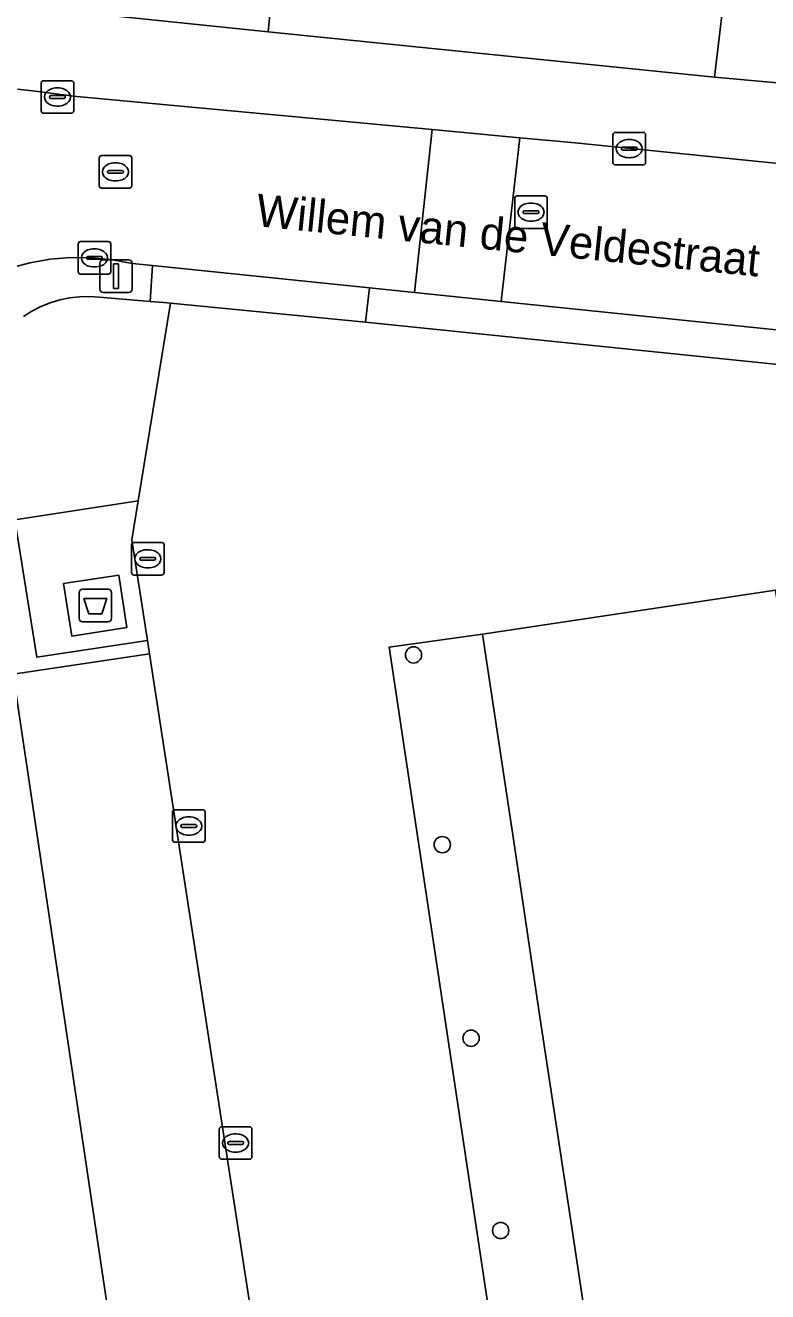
# Model space of a CAD drawing. Extents: x 163008 to 163854, y 382777 to 383982.
# Drawn here: x 163190.97 to 163213.77, y 383368.33 to 383407.26 of the extents above; entities that cross this region are included whole.
import ezdxf

# ---------------------------------------------------------------- set-up
doc = ezdxf.new("R2010")
doc.units = 0
for name, color, linetype in [('IMGEO_Afval_apart_plaats', 7, 'Continuous'), ('IMGEO_Groenvoorziening', 7, 'Continuous'), ('IMGEO_Kolk', 7, 'Continuous'), ('IMGEO_Lichtmast', 7, 'Continuous'), ('IMGEO_Openbare_ruimte_label', 7, 'Continuous'), ('IMGEO_Pand', 7, 'Continuous'), ('IMGEO_Pand_overbouw', 7, 'Continuous'), ('IMGEO_Parkeervlak_halfverhard', 7, 'Continuous'), ('IMGEO_Rijbaan_lokaal_open', 7, 'Continuous'), ('IMGEO_Rioolput', 7, 'Continuous'), ('IMGEO_Voetpad_gesloten', 7, 'Continuous'), ('IMGEO_Voetpad_open', 7, 'Continuous')]:
    doc.layers.add(name, color=color, linetype=linetype)

msp = doc.modelspace()

# ---------------------------------------------------------------- linework, layer by layer
at = {"layer": 'IMGEO_Afval_apart_plaats'}
for p, q in [((163192.72, 383389.926), (163193.51, 383389.926)), ((163193.51, 383389.926), (163192.72, 383389.926)), ((163192.62, 383389.026), (163192.62, 383389.826)), ((163192.62, 383389.826), (163192.62, 383389.026)), ((163193.61, 383389.826), (163193.61, 383389.026)), ((163193.61, 383389.026), (163193.61, 383389.826)), ((163193.51, 383388.926), (163192.72, 383388.926)), ((163192.72, 383388.926), (163193.51, 383388.926))]:
    msp.add_line(p, q, dxfattribs=at)
msp.add_lwpolyline([(163192.763, 383389.64), (163193.467, 383389.64), (163193.318, 383389.17), (163192.912, 383389.17), (163192.763, 383389.64)], dxfattribs=at)
for centre, start, end in [((163192.72, 383389.826), 90, 180), ((163192.72, 383389.826), 90, 180), ((163193.51, 383389.826), 0, 90), ((163193.51, 383389.826), 360, 90), ((163192.72, 383389.026), 180, 270), ((163192.72, 383389.026), 180, 270), ((163193.51, 383389.026), 270, 0), ((163193.51, 383389.026), 270, 0)]:
    msp.add_arc(centre, 0.1, start, end, dxfattribs=at)
at = {"layer": 'IMGEO_Groenvoorziening'}
msp.add_lwpolyline([(163211.181, 383449.868), (163215.688, 383449.397), (163215.941, 383451.456), (163217.477, 383451.284), (163217.785, 383454.728), (163209.947, 383464.725), (163204.688, 383471.425), (163204.272, 383467.657), (163204.373, 383467.646), (163204.31, 383467.05), (163198.432, 383407.063), (163212.145, 383405.663), (163212.537, 383409.043), (163206.93, 383409.63)], close=True, dxfattribs=at)
for points in [[(163191.187, 383407.81), (163198.432, 383407.063), (163204.31, 383467.05)], [(163190.596, 383387.318), (163194.782, 383387.944), (163194.718, 383388.353), (163191.317, 383387.834), (163190.642, 383392.056), (163194.437, 383392.642), (163195.429, 383398.72), (163195.211, 383398.741), (163194.8, 383398.775), (163193.244, 383398.905), (163192.937, 383398.925), (163192.629, 383398.918), (163192.323, 383398.883), (163192.022, 383398.821), (163191.727, 383398.732), (163191.442, 383398.617), (163191.167, 383398.478), (163190.907, 383398.314)]]:
    msp.add_lwpolyline(points, dxfattribs=at)
at = {"layer": 'IMGEO_Kolk'}
for p, q in [((163191.526, 383405.558), (163192.378, 383405.558)), ((163191.451, 383404.632), (163191.451, 383405.484)), ((163191.939, 383405.338), (163191.964, 383405.338)), ((163192.452, 383405.484), (163192.452, 383404.632)), ((163191.71, 383405.052), (163191.71, 383405.064)), ((163192.148, 383405.015), (163191.75, 383405.015)), ((163191.753, 383405.101), (163192.151, 383405.101)), ((163191.962, 383404.778), (163191.937, 383404.778)), ((163192.194, 383405.064), (163192.194, 383405.052)), ((163192.378, 383404.558), (163191.526, 383404.558)), ((163209.096, 383403.971), (163209.948, 383403.971)), ((163209.021, 383403.045), (163209.021, 383403.897)), ((163209.509, 383403.751), (163209.534, 383403.751)), ((163210.022, 383403.897), (163210.022, 383403.045)), ((163209.28, 383403.465), (163209.28, 383403.477)), ((163209.718, 383403.428), (163209.32, 383403.428)), ((163209.323, 383403.514), (163209.721, 383403.514)), ((163209.532, 383403.191), (163209.507, 383403.191)), ((163209.764, 383403.477), (163209.764, 383403.465)), ((163209.948, 383402.971), (163209.096, 383402.971)), ((163192.588, 383399.687), (163192.588, 383400.539)), ((163192.663, 383400.613), (163193.515, 383400.613)), ((163193.589, 383400.539), (163193.589, 383399.687)), ((163192.847, 383400.107), (163192.847, 383400.119)), ((163193.285, 383400.07), (163192.887, 383400.07)), ((163192.89, 383400.156), (163193.288, 383400.156)), ((163193.076, 383400.393), (163193.101, 383400.393)), ((163193.331, 383400.119), (163193.331, 383400.107)), ((163193.099, 383399.833), (163193.074, 383399.833)), ((163193.515, 383399.613), (163192.663, 383399.613)), ((163194.227, 383390.437), (163194.227, 383391.289)), ((163194.302, 383391.363), (163195.154, 383391.363)), ((163194.715, 383391.143), (163194.74, 383391.143)), ((163195.228, 383391.289), (163195.228, 383390.437)), ((163194.486, 383390.857), (163194.486, 383390.869)), ((163194.924, 383390.82), (163194.526, 383390.82)), ((163194.529, 383390.906), (163194.927, 383390.906)), ((163194.97, 383390.869), (163194.97, 383390.857)), ((163195.154, 383390.363), (163194.302, 383390.363)), ((163194.738, 383390.583), (163194.713, 383390.583)), ((163195.489, 383382.223), (163195.489, 383383.075)), ((163195.564, 383383.149), (163196.416, 383383.149)), ((163195.977, 383382.929), (163196.002, 383382.929)), ((163196.49, 383383.075), (163196.49, 383382.223)), ((163195.748, 383382.643), (163195.748, 383382.655)), ((163196.186, 383382.606), (163195.788, 383382.606)), ((163195.791, 383382.692), (163196.189, 383382.692)), ((163196.232, 383382.655), (163196.232, 383382.643)), ((163196.416, 383382.149), (163195.564, 383382.149)), ((163196, 383382.369), (163195.975, 383382.369)), ((163196.926, 383372.478), (163196.926, 383373.33)), ((163197.001, 383373.404), (163197.853, 383373.404)), ((163197.927, 383373.33), (163197.927, 383372.478)), ((163197.185, 383372.898), (163197.185, 383372.91)), ((163197.623, 383372.861), (163197.225, 383372.861)), ((163197.228, 383372.947), (163197.626, 383372.947)), ((163197.414, 383373.184), (163197.439, 383373.184)), ((163197.669, 383372.91), (163197.669, 383372.898)), ((163197.437, 383372.624), (163197.412, 383372.624)), ((163197.853, 383372.404), (163197.001, 383372.404))]:
    msp.add_line(p, q, dxfattribs=at)
for points in [[(163191.526, 383405.558), (163192.378, 383405.558)], [(163191.451, 383404.632), (163191.451, 383405.484)], [(163192.452, 383405.484), (163192.452, 383404.632)], [(163192.378, 383404.558), (163191.526, 383404.558)], [(163209.096, 383403.971), (163209.948, 383403.971)], [(163209.021, 383403.045), (163209.021, 383403.897)], [(163210.022, 383403.897), (163210.022, 383403.045)], [(163209.948, 383402.971), (163209.096, 383402.971)], [(163192.588, 383399.687), (163192.588, 383400.539)], [(163192.663, 383400.613), (163193.515, 383400.613)], [(163193.589, 383400.539), (163193.589, 383399.687)], [(163193.515, 383399.613), (163192.663, 383399.613)], [(163194.227, 383390.437), (163194.227, 383391.289)], [(163194.302, 383391.363), (163195.154, 383391.363)], [(163195.228, 383391.289), (163195.228, 383390.437)], [(163195.154, 383390.363), (163194.302, 383390.363)], [(163195.489, 383382.223), (163195.489, 383383.075)], [(163195.564, 383383.149), (163196.416, 383383.149)], [(163196.49, 383383.075), (163196.49, 383382.223)], [(163196.416, 383382.149), (163195.564, 383382.149)], [(163196.926, 383372.478), (163196.926, 383373.33)], [(163197.001, 383373.404), (163197.853, 383373.404)], [(163197.927, 383373.33), (163197.927, 383372.478)], [(163197.853, 383372.404), (163197.001, 383372.404)]]:
    msp.add_lwpolyline(points, dxfattribs=at)
for centre, radius, start, end in [((163191.528, 383405.482), 0.0765, 91.552, 178.448), ((163191.528, 383405.482), 0.0765, 91.552, 178.448), ((163192.376, 383405.482), 0.0765, 1.552, 88.448), ((163192.376, 383405.482), 0.0765, 1.552, 88.448), ((163191.75, 383405.061), 0.0403, 85.8775, 175.7526), ((163191.747, 383405.051), 0.0366, 178.938, 274.7102), ((163192.151, 383405.058), 0.043, 264.8664, 352.4533), ((163192.155, 383405.063), 0.0386, 1.7309, 96.639), ((163191.528, 383404.634), 0.0765, 181.552, 268.448), ((163191.528, 383404.634), 0.0765, 181.552, 268.448), ((163192.376, 383404.634), 0.0765, 271.552, 358.448), ((163192.376, 383404.634), 0.0765, 271.552, 358.448), ((163209.098, 383403.895), 0.0765, 91.552, 178.448), ((163209.098, 383403.895), 0.0765, 91.552, 178.448), ((163209.946, 383403.895), 0.0765, 1.552, 88.448), ((163209.946, 383403.895), 0.0765, 1.552, 88.448), ((163209.32, 383403.474), 0.0403, 85.8775, 175.7526), ((163209.317, 383403.464), 0.0366, 178.938, 274.7102), ((163209.721, 383403.471), 0.043, 264.8664, 352.4533), ((163209.725, 383403.476), 0.0386, 1.7309, 96.639), ((163209.098, 383403.047), 0.0765, 181.552, 268.448), ((163209.098, 383403.047), 0.0765, 181.552, 268.448), ((163209.946, 383403.047), 0.0765, 271.552, 358.448), ((163209.946, 383403.047), 0.0765, 271.552, 358.448), ((163192.665, 383400.537), 0.0765, 91.552, 178.448), ((163192.665, 383400.537), 0.0765, 91.552, 178.448), ((163193.513, 383400.537), 0.0765, 1.552, 88.448), ((163193.513, 383400.537), 0.0765, 1.552, 88.448), ((163192.887, 383400.116), 0.0403, 85.8775, 175.7526), ((163192.884, 383400.106), 0.0366, 178.938, 274.7102), ((163193.288, 383400.113), 0.043, 264.8664, 352.4533), ((163193.292, 383400.118), 0.0386, 1.7309, 96.639), ((163192.665, 383399.689), 0.0765, 181.552, 268.448), ((163192.665, 383399.689), 0.0765, 181.552, 268.448), ((163193.513, 383399.689), 0.0765, 271.552, 358.448), ((163193.513, 383399.689), 0.0765, 271.552, 358.448), ((163194.304, 383391.287), 0.0765, 91.552, 178.448), ((163194.304, 383391.287), 0.0765, 91.552, 178.448), ((163195.152, 383391.287), 0.0765, 1.552, 88.448), ((163195.152, 383391.287), 0.0765, 1.552, 88.448), ((163194.526, 383390.866), 0.0403, 85.8775, 175.7526), ((163194.523, 383390.856), 0.0366, 178.938, 274.7102), ((163194.927, 383390.863), 0.043, 264.8664, 352.4533), ((163194.931, 383390.868), 0.0386, 1.7309, 96.639), ((163194.304, 383390.439), 0.0765, 181.552, 268.448), ((163194.304, 383390.439), 0.0765, 181.552, 268.448), ((163195.152, 383390.439), 0.0765, 271.552, 358.448), ((163195.152, 383390.439), 0.0765, 271.552, 358.448), ((163195.566, 383383.073), 0.0765, 91.552, 178.448), ((163195.566, 383383.073), 0.0765, 91.552, 178.448), ((163196.414, 383383.073), 0.0765, 1.552, 88.448), ((163196.414, 383383.073), 0.0765, 1.552, 88.448), ((163195.788, 383382.652), 0.0403, 85.8775, 175.7526), ((163195.785, 383382.642), 0.0366, 178.938, 274.7102), ((163196.189, 383382.649), 0.043, 264.8664, 352.4533), ((163196.193, 383382.654), 0.0386, 1.7309, 96.639), ((163195.566, 383382.225), 0.0765, 181.552, 268.448), ((163195.566, 383382.225), 0.0765, 181.552, 268.448), ((163196.414, 383382.225), 0.0765, 271.552, 358.448), ((163196.414, 383382.225), 0.0765, 271.552, 358.448), ((163197.003, 383373.328), 0.0765, 91.552, 178.448), ((163197.003, 383373.328), 0.0765, 91.552, 178.448), ((163197.851, 383373.328), 0.0765, 1.552, 88.448), ((163197.851, 383373.328), 0.0765, 1.552, 88.448), ((163197.225, 383372.907), 0.0403, 85.8775, 175.7526), ((163197.222, 383372.897), 0.0366, 178.938, 274.7102), ((163197.626, 383372.904), 0.043, 264.8664, 352.4533), ((163197.63, 383372.909), 0.0386, 1.7309, 96.639), ((163197.003, 383372.48), 0.0765, 181.552, 268.448), ((163197.003, 383372.48), 0.0765, 181.552, 268.448), ((163197.851, 383372.48), 0.0765, 271.552, 358.448), ((163197.851, 383372.48), 0.0765, 271.552, 358.448)]:
    msp.add_arc(centre, radius, start, end, dxfattribs=at)
for centre, major_axis, ratio, start_param, end_param in [((163191.938, 383405.058), (-0.387, 0.002), 0.722429, 4.712389, 7.853982), ((163191.963, 383405.058), (-0.39, 0.002), 0.717154, 1.570796, 4.712389), ((163209.508, 383403.471), (-0.387, 0.002), 0.722429, 4.712389, 7.853982), ((163209.533, 383403.471), (-0.39, 0.002), 0.717154, 1.570796, 4.712389), ((163193.075, 383400.113), (-0.387, 0.002), 0.722429, 4.712389, 7.853982), ((163193.1, 383400.113), (-0.39, 0.002), 0.717154, 1.570796, 4.712389), ((163194.714, 383390.863), (-0.387, 0.002), 0.722429, 4.712389, 7.853982), ((163194.739, 383390.863), (-0.39, 0.002), 0.717154, 1.570796, 4.712389), ((163195.976, 383382.649), (-0.387, 0.002), 0.722429, 4.712389, 7.853982), ((163196.001, 383382.649), (-0.39, 0.002), 0.717154, 1.570796, 4.712389), ((163197.413, 383372.904), (-0.387, 0.002), 0.722429, 4.712389, 7.853982), ((163197.438, 383372.904), (-0.39, 0.002), 0.717154, 1.570796, 4.712389)]:
    msp.add_ellipse(centre, major_axis=major_axis, ratio=ratio, start_param=start_param, end_param=end_param, dxfattribs=at)
at = {"layer": 'IMGEO_Lichtmast'}
for p, q in [((163193.357, 383400.05), (163194.147, 383400.05)), ((163194.147, 383400.05), (163193.357, 383400.05)), ((163193.257, 383399.15), (163193.257, 383399.95)), ((163193.257, 383399.95), (163193.257, 383399.15)), ((163194.247, 383399.95), (163194.247, 383399.15)), ((163194.247, 383399.15), (163194.247, 383399.95)), ((163194.147, 383399.05), (163193.357, 383399.05)), ((163193.357, 383399.05), (163194.147, 383399.05))]:
    msp.add_line(p, q, dxfattribs=at)
msp.add_lwpolyline([(163193.677, 383399.925), (163193.827, 383399.925), (163193.827, 383399.175), (163193.677, 383399.175), (163193.677, 383399.925)], dxfattribs=at)
for centre, start, end in [((163193.357, 383399.95), 90, 180), ((163193.357, 383399.95), 90, 180), ((163194.147, 383399.95), 0, 90), ((163194.147, 383399.95), 360, 90), ((163193.357, 383399.15), 180, 270), ((163193.357, 383399.15), 180, 270), ((163194.147, 383399.15), 270, 0), ((163194.147, 383399.15), 270, 0)]:
    msp.add_arc(centre, 0.1, start, end, dxfattribs=at)
at = {"layer": 'IMGEO_Pand'}
msp.add_lwpolyline([(163223.07, 383329.86), (163222.117, 383336.203), (163221.206, 383342.268), (163219.424, 383354.102), (163218.489, 383360.307), (163217.672, 383365.721), (163216.729, 383372), (163215.811, 383378.119), (163214.019, 383389.896), (163205.008, 383388.541), (163205.973, 383382.176), (163206.776, 383376.781), (163207.704, 383370.643), (163208.652, 383364.371), (163209.451, 383358.986), (163210.397, 383352.744), (163211.368, 383346.337), (163212.171, 383340.926), (163213.089, 383334.846), (163214.042, 383328.531)], dxfattribs=at)
for centre, start, end in [((163202.893, 383387.908), 90, 270), ((163202.893, 383387.908), 270, 90), ((163203.777, 383382.075), 90, 270), ((163203.777, 383382.075), 270, 90), ((163204.662, 383376.126), 90, 270), ((163204.662, 383376.126), 270, 90), ((163205.571, 383370.214), 90, 270), ((163205.571, 383370.214), 270, 90)]:
    msp.add_arc(centre, 0.25, start, end, dxfattribs=at)
at = {"layer": 'IMGEO_Pand_overbouw'}
msp.add_lwpolyline([(163206.776, 383376.781), (163205.973, 383382.176), (163205.008, 383388.541), (163202.14, 383388.145), (163215.602, 383298.476), (163218.49, 383298.916), (163217.531, 383305.316), (163216.715, 383310.736), (163215.782, 383316.947), (163214.042, 383328.531), (163213.089, 383334.846), (163212.171, 383340.926), (163211.368, 383346.337), (163210.397, 383352.744), (163209.451, 383358.986), (163208.652, 383364.371), (163207.704, 383370.643)], close=True, dxfattribs=at)
at = {"layer": 'IMGEO_Parkeervlak_halfverhard'}
msp.add_lwpolyline([(163203.383, 383301.381), (163204.031, 383296.956), (163208.685, 383297.697), (163194.782, 383387.944), (163190.596, 383387.318)], close=True, dxfattribs=at)
at = {"layer": 'IMGEO_Rijbaan_lokaal_open'}
for points in [[(163190.489, 383399.799), (163191.103, 383399.963), (163191.729, 383400.071), (163192.362, 383400.123), (163192.997, 383400.118), (163193.63, 383400.057), (163194.254, 383399.939), (163194.875, 383399.875), (163201.537, 383399.188), (163202.925, 383399.045), (163203.464, 383404.058), (163192.544, 383405.077), (163191.182, 383405.246), (163190.727, 383405.303)], [(163244.897, 383399.882), (163207.861, 383403.648), (163206.155, 383403.807), (163205.589, 383398.77), (163238.626, 383395.365), (163239.912, 383395.232), (163240.157, 383395.176)]]:
    msp.add_lwpolyline(points, dxfattribs=at)
for points in [[(163206.155, 383403.807), (163203.464, 383404.058), (163202.925, 383399.045), (163205.589, 383398.77)], [(163209.321, 383293.567), (163210.358, 383287.248), (163231.919, 383290.725), (163233.555, 383291.767), (163238.641, 383291.287), (163238.685, 383291.68), (163239.267, 383297.262), (163239.357, 383298.129), (163234.446, 383298.587), (163229.454, 383296.513), (163216.105, 383294.476), (163215.602, 383298.476), (163202.14, 383388.145), (163205.008, 383388.541), (163214.019, 383389.896), (163215.316, 383390.105), (163214.391, 383396.806), (163201.42, 383398.14), (163195.429, 383398.72), (163194.437, 383392.642), (163194.239, 383391.448), (163194.718, 383388.353), (163194.782, 383387.944), (163208.685, 383297.697)]]:
    msp.add_lwpolyline(points, close=True, dxfattribs=at)
at = {"layer": 'IMGEO_Rioolput'}
for p, q in [((163193.235, 383402.331), (163193.235, 383403.183)), ((163193.31, 383403.257), (163194.162, 383403.257)), ((163194.236, 383403.183), (163194.236, 383402.331)), ((163193.537, 383402.8), (163193.935, 383402.8)), ((163193.723, 383403.037), (163193.748, 383403.037)), ((163193.494, 383402.751), (163193.494, 383402.763)), ((163193.932, 383402.714), (163193.534, 383402.714)), ((163193.746, 383402.477), (163193.721, 383402.477)), ((163193.978, 383402.763), (163193.978, 383402.751)), ((163194.162, 383402.257), (163193.31, 383402.257)), ((163206.077, 383402.018), (163206.929, 383402.018)), ((163206.002, 383401.092), (163206.002, 383401.944)), ((163206.49, 383401.798), (163206.515, 383401.798)), ((163207.003, 383401.944), (163207.003, 383401.092)), ((163206.261, 383401.512), (163206.261, 383401.524)), ((163206.699, 383401.475), (163206.301, 383401.475)), ((163206.304, 383401.561), (163206.702, 383401.561)), ((163206.513, 383401.238), (163206.488, 383401.238)), ((163206.745, 383401.524), (163206.745, 383401.512)), ((163206.929, 383401.018), (163206.077, 383401.018))]:
    msp.add_line(p, q, dxfattribs=at)
for points in [[(163193.235, 383402.331), (163193.235, 383403.183)], [(163193.31, 383403.257), (163194.162, 383403.257)], [(163194.236, 383403.183), (163194.236, 383402.331)], [(163194.162, 383402.257), (163193.31, 383402.257)], [(163206.077, 383402.018), (163206.929, 383402.018)], [(163206.002, 383401.092), (163206.002, 383401.944)], [(163207.003, 383401.944), (163207.003, 383401.092)], [(163206.929, 383401.018), (163206.077, 383401.018)]]:
    msp.add_lwpolyline(points, dxfattribs=at)
for centre, radius, start, end in [((163193.312, 383403.181), 0.0765, 91.552, 178.448), ((163193.312, 383403.181), 0.0765, 91.552, 178.448), ((163194.16, 383403.181), 0.0765, 1.552, 88.448), ((163194.16, 383403.181), 0.0765, 1.552, 88.448), ((163193.534, 383402.76), 0.0403, 85.8775, 175.7526), ((163193.939, 383402.762), 0.0386, 1.7309, 96.639), ((163193.531, 383402.75), 0.0366, 178.938, 274.7102), ((163193.935, 383402.757), 0.043, 264.8664, 352.4533), ((163193.312, 383402.333), 0.0765, 181.552, 268.448), ((163193.312, 383402.333), 0.0765, 181.552, 268.448), ((163194.16, 383402.333), 0.0765, 271.552, 358.448), ((163194.16, 383402.333), 0.0765, 271.552, 358.448), ((163206.079, 383401.942), 0.0765, 91.552, 178.448), ((163206.079, 383401.942), 0.0765, 91.552, 178.448), ((163206.927, 383401.942), 0.0765, 1.552, 88.448), ((163206.927, 383401.942), 0.0765, 1.552, 88.448), ((163206.301, 383401.521), 0.0403, 85.8775, 175.7526), ((163206.298, 383401.511), 0.0366, 178.938, 274.7102), ((163206.702, 383401.518), 0.043, 264.8664, 352.4533), ((163206.706, 383401.523), 0.0386, 1.7309, 96.639), ((163206.079, 383401.094), 0.0765, 181.552, 268.448), ((163206.079, 383401.094), 0.0765, 181.552, 268.448), ((163206.927, 383401.094), 0.0765, 271.552, 358.448), ((163206.927, 383401.094), 0.0765, 271.552, 358.448)]:
    msp.add_arc(centre, radius, start, end, dxfattribs=at)
for centre, major_axis, ratio, start_param, end_param in [((163193.722, 383402.757), (-0.387, 0.002), 0.722429, 4.712389, 7.853982), ((163193.747, 383402.757), (-0.39, 0.002), 0.717154, 1.570796, 4.712389), ((163206.489, 383401.518), (-0.387, 0.002), 0.722429, 4.712389, 7.853982), ((163206.514, 383401.518), (-0.39, 0.002), 0.717154, 1.570796, 4.712389)]:
    msp.add_ellipse(centre, major_axis=major_axis, ratio=ratio, start_param=start_param, end_param=end_param, dxfattribs=at)
at = {"layer": 'IMGEO_Voetpad_gesloten'}
msp.add_lwpolyline([(163193.838, 383390.364), (163192.141, 383390.101), (163192.391, 383388.489), (163194.088, 383388.752)], close=True, dxfattribs=at)
at = {"layer": 'IMGEO_Voetpad_open'}
for points in [[(163221.075, 383408.13), (163220.482, 383408.212), (163212.537, 383409.043), (163212.145, 383405.663), (163220.785, 383404.884), (163220.813, 383405.195), (163220.859, 383405.716)], [(163201.42, 383398.14), (163201.537, 383399.188), (163194.875, 383399.875), (163194.8, 383398.775), (163195.211, 383398.741), (163195.429, 383398.72)], [(163205.589, 383398.77), (163202.925, 383399.045), (163201.537, 383399.188), (163201.42, 383398.14), (163214.391, 383396.806), (163235.287, 383394.655), (163238.513, 383394.323), (163238.626, 383395.365)], [(163194.239, 383391.448), (163194.437, 383392.642), (163190.642, 383392.056), (163191.317, 383387.834), (163194.718, 383388.353)], [(163192.391, 383388.489), (163192.141, 383390.101), (163193.838, 383390.364), (163194.088, 383388.752)], [(163215.602, 383298.476), (163218.49, 383298.916), (163217.531, 383305.316), (163216.715, 383310.736), (163215.782, 383316.947), (163214.042, 383328.531), (163213.089, 383334.846), (163212.171, 383340.926), (163211.368, 383346.337), (163210.397, 383352.744), (163209.451, 383358.986), (163208.652, 383364.371), (163207.704, 383370.643), (163206.776, 383376.781), (163205.973, 383382.176), (163205.008, 383388.541), (163202.14, 383388.145)]]:
    msp.add_lwpolyline(points, close=True, dxfattribs=at)
for points in [[(163220.785, 383404.884), (163212.145, 383405.663), (163198.432, 383407.063), (163191.187, 383407.81)], [(163190.727, 383405.303), (163191.182, 383405.246), (163192.544, 383405.077), (163203.464, 383404.058), (163206.155, 383403.807), (163207.861, 383403.648), (163244.897, 383399.882)], [(163190.907, 383398.314), (163191.167, 383398.478), (163191.442, 383398.617), (163191.727, 383398.732), (163192.022, 383398.821), (163192.323, 383398.883), (163192.629, 383398.918), (163192.937, 383398.925), (163193.244, 383398.905), (163194.8, 383398.775), (163194.875, 383399.875), (163194.254, 383399.939), (163193.63, 383400.057), (163192.997, 383400.118), (163192.362, 383400.123), (163191.729, 383400.071), (163191.103, 383399.963), (163190.489, 383399.799)], [(163205.198, 383285.869), (163204.638, 383292.807), (163204.031, 383296.956), (163203.383, 383301.381), (163190.596, 383387.318)]]:
    msp.add_lwpolyline(points, dxfattribs=at)
for centre, start, end in [((163202.893, 383387.908), 90, 270), ((163202.893, 383387.908), 270, 90), ((163203.777, 383382.075), 90, 270), ((163203.777, 383382.075), 270, 90), ((163204.662, 383376.126), 90, 270), ((163204.662, 383376.126), 270, 90), ((163205.571, 383370.214), 90, 270), ((163205.571, 383370.214), 270, 90)]:
    msp.add_arc(centre, 0.25, start, end, dxfattribs=at)

# ---------------------------------------------------------------- texts
at = {"layer": 'IMGEO_Openbare_ruimte_label'}
msp.add_text('Willem van de Veldestraat', height=1, rotation=354.2609, dxfattribs=at).set_placement((163198.019, 383401.092))
msp.add_text('Willem van de Veldestraat', height=1, rotation=354.2609, dxfattribs=at).set_placement((163198.019, 383401.092))

doc.saveas('drawing.dxf')
